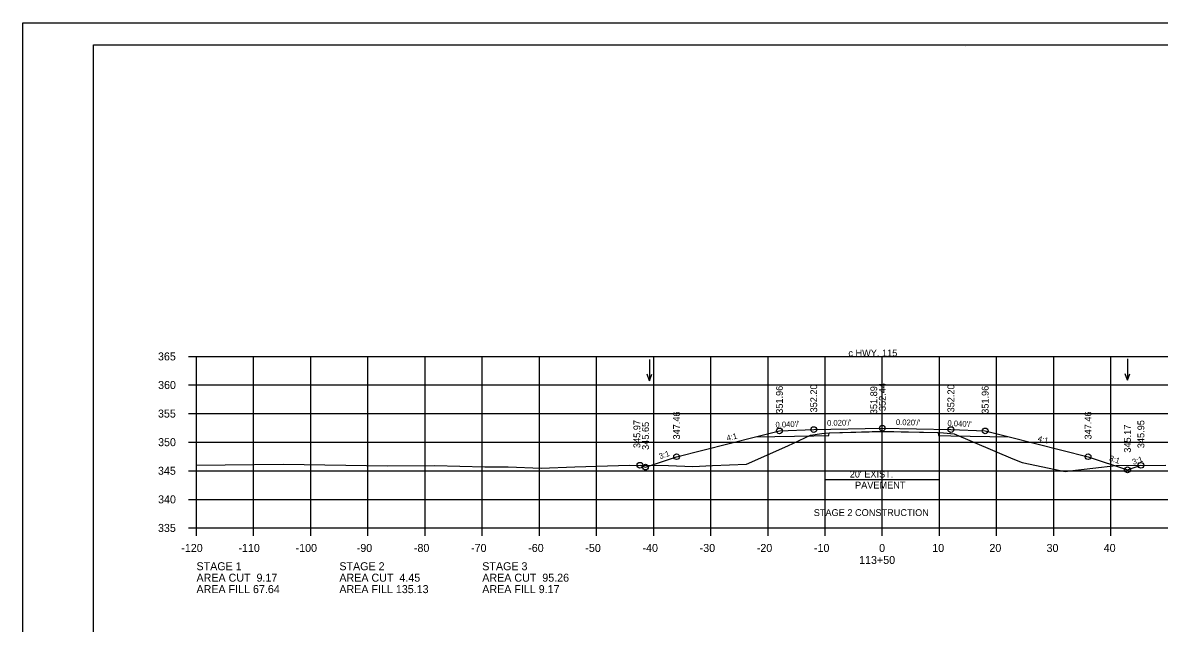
# Model space of a CAD drawing. Extents: x 1630712 to 1632516, y 782146 to 785403.
# Drawn here: x 1632182.6 to 1632381.4, y 784871.6 to 784976.7 of the extents above; entities that cross this region are included whole.
import ezdxf

# ---------------------------------------------------------------- set-up
doc = ezdxf.new("R2010")
doc.units = 0
for name, color, linetype in [('Notes', 7, 'Continuous'), ('R_Alt Surface', 7, 'Continuous'), ('R_Axis', 7, 'Continuous'), ('R_Axis Annot', 7, 'Continuous'), ('R_Border', 7, 'Continuous'), ('R_Exist Surface', 7, 'Continuous'), ('R_Fin Surface', 7, 'Continuous'), ('R_Grid', 7, 'Continuous'), ('R_No Plot', 7, 'Continuous'), ('R_Water Annot', 7, 'Continuous'), ('R_Xsect Elev', 7, 'Continuous'), ('R_Xsect Slope', 7, 'Continuous')]:
    doc.layers.add(name, color=color, linetype=linetype)

msp = doc.modelspace()

# ---------------------------------------------------------------- linework, layer by layer
at = {"layer": 'Notes'}
for p, q in [((1632322.96, 784895.06), (1632322.96, 784898.46)), ((1632342.96, 784895.06), (1632342.96, 784898.46)), ((1632322.96, 784896.76), (1632342.96, 784896.76))]:
    msp.add_line(p, q, dxfattribs=at)
at = {"layer": 'R_Alt Surface'}
msp.add_lwpolyline([(1632310.79, 784904.23), (1632320.96, 784904.43), (1632323.62, 784904.48), (1632323.67, 784904.94), (1632333.01, 784905.2), (1632342.74, 784905), (1632342.79, 784904.48), (1632344.96, 784904.43), (1632355.14, 784904.23)], dxfattribs=at)
at = {"layer": 'R_Axis'}
for p, q in [((1632211.56, 784918.31), (1632212.96, 784918.31)), ((1632212.96, 784888.31), (1632212.96, 784918.31)), ((1632211.56, 784913.31), (1632212.96, 784913.31)), ((1632211.56, 784908.31), (1632212.96, 784908.31)), ((1632211.56, 784903.31), (1632212.96, 784903.31)), ((1632211.56, 784898.31), (1632212.96, 784898.31)), ((1632211.56, 784893.31), (1632212.96, 784893.31)), ((1632211.56, 784888.31), (1632212.96, 784888.31)), ((1632212.96, 784888.31), (1632492.96, 784888.31)), ((1632212.96, 784886.91), (1632212.96, 784888.31)), ((1632222.96, 784886.91), (1632222.96, 784888.31)), ((1632232.96, 784886.91), (1632232.96, 784888.31)), ((1632242.96, 784886.91), (1632242.96, 784888.31)), ((1632252.96, 784886.91), (1632252.96, 784888.31)), ((1632262.96, 784886.91), (1632262.96, 784888.31)), ((1632272.96, 784886.91), (1632272.96, 784888.31)), ((1632282.96, 784886.91), (1632282.96, 784888.31)), ((1632292.96, 784886.91), (1632292.96, 784888.31)), ((1632302.96, 784886.91), (1632302.96, 784888.31)), ((1632312.96, 784886.91), (1632312.96, 784888.31)), ((1632322.96, 784886.91), (1632322.96, 784888.31)), ((1632332.96, 784886.91), (1632332.96, 784888.31)), ((1632342.96, 784886.91), (1632342.96, 784888.31)), ((1632352.96, 784886.91), (1632352.96, 784888.31)), ((1632362.96, 784886.91), (1632362.96, 784888.31)), ((1632372.96, 784886.91), (1632372.96, 784888.31))]:
    msp.add_line(p, q, dxfattribs=at)
at = {"layer": 'R_Border'}
for p, q in [((1632194.96, 784972.77), (1632511.14, 784972.77)), ((1632194.96, 784767.31), (1632194.96, 784972.77)), ((1632347.48, 784972.51), (1632347.48, 784972.51)), ((1632347.48, 784972.51), (1632347.48, 784972.51))]:
    msp.add_line(p, q, dxfattribs=at)
at = {"layer": 'R_Exist Surface'}
msp.add_lwpolyline([(1632212.96, 784899.31), (1632217.97, 784899.36), (1632228.2, 784899.47), (1632246.32, 784899.18), (1632254.66, 784899.23), (1632263.41, 784899), (1632267.5, 784899.02), (1632273.29, 784898.75), (1632279.16, 784899.02), (1632288.73, 784899.31), (1632295.53, 784899.21), (1632299.83, 784899.07), (1632303.24, 784899.21), (1632309.21, 784899.47), (1632316.4, 784902.69), (1632320.4, 784904.53), (1632322.39, 784904.8), (1632323.67, 784904.94), (1632331.17, 784905.15), (1632333.01, 784905.2), (1632335, 784905.16), (1632342.74, 784905), (1632343.68, 784904.93), (1632345.55, 784904.77), (1632355.79, 784900.42), (1632357.41, 784899.76), (1632364.37, 784898.31), (1632364.95, 784898.21), (1632365.78, 784898.32), (1632373.84, 784899.25), (1632382.54, 784899.26)], dxfattribs=at)
at = {"layer": 'R_Fin Surface'}
msp.add_lwpolyline([(1632290.55, 784899.28), (1632291.52, 784898.96), (1632296.96, 784900.77), (1632310.79, 784904.23), (1632314.96, 784905.27), (1632320.96, 784905.51), (1632332.96, 784905.75), (1632344.96, 784905.51), (1632350.96, 784905.27), (1632355.14, 784904.23), (1632368.96, 784900.77), (1632375.86, 784898.47), (1632378.21, 784899.26)], dxfattribs=at)
at = {"layer": 'R_Grid'}
for p, q in [((1632212.96, 784918.31), (1632492.96, 784918.31)), ((1632212.96, 784888.31), (1632212.96, 784918.31)), ((1632222.96, 784888.31), (1632222.96, 784918.31)), ((1632232.96, 784888.31), (1632232.96, 784918.31)), ((1632242.96, 784888.31), (1632242.96, 784918.31)), ((1632252.96, 784888.31), (1632252.96, 784918.31)), ((1632262.96, 784888.31), (1632262.96, 784918.31)), ((1632272.96, 784888.31), (1632272.96, 784918.31)), ((1632282.96, 784888.31), (1632282.96, 784918.31)), ((1632292.96, 784888.31), (1632292.96, 784918.31)), ((1632302.96, 784888.31), (1632302.96, 784918.31)), ((1632312.96, 784888.31), (1632312.96, 784918.31)), ((1632322.96, 784888.31), (1632322.96, 784918.31)), ((1632332.96, 784888.31), (1632332.96, 784918.31)), ((1632342.96, 784888.31), (1632342.96, 784918.31)), ((1632352.96, 784888.31), (1632352.96, 784918.31)), ((1632362.96, 784888.31), (1632362.96, 784918.31)), ((1632372.96, 784888.31), (1632372.96, 784918.31)), ((1632212.96, 784913.31), (1632492.96, 784913.31)), ((1632212.96, 784908.31), (1632492.96, 784908.31)), ((1632212.96, 784903.31), (1632492.96, 784903.31)), ((1632212.96, 784898.31), (1632492.96, 784898.31)), ((1632212.96, 784893.31), (1632492.96, 784893.31)), ((1632212.96, 784888.31), (1632492.96, 784888.31))]:
    msp.add_line(p, q, dxfattribs=at)
at = {"layer": 'R_No Plot'}
msp.add_line((1632182.56, 784976.66), (1632515.9, 784976.66), dxfattribs=at)
msp.add_lwpolyline([(1632182.56, 784976.66), (1632515.9, 784976.66), (1632515.9, 784763.32), (1632182.56, 784763.32)], close=True, dxfattribs=at)
for centre in [(1632320.96, 784905.51), (1632332.96, 784905.75), (1632344.96, 784905.51), (1632314.96, 784905.27), (1632350.96, 784905.27), (1632296.96, 784900.77), (1632368.96, 784900.77), (1632290.55, 784899.28), (1632291.52, 784898.96), (1632375.86, 784898.47), (1632378.21, 784899.26)]:
    msp.add_circle(centre, 0.5, dxfattribs=at)
at = {"layer": 'R_Water Annot'}
for p, q in [((1632375.86, 784917.91), (1632375.86, 784914.14)), ((1632292.24, 784917.79), (1632292.24, 784914.02)), ((1632292.24, 784914.02), (1632291.82, 784915.18)), ((1632292.24, 784914.02), (1632292.66, 784915.18)), ((1632375.86, 784914.14), (1632375.44, 784915.29)), ((1632375.86, 784914.14), (1632376.28, 784915.29))]:
    msp.add_line(p, q, dxfattribs=at)

# ---------------------------------------------------------------- texts
at = {"layer": 'Notes'}
for s, p in [('c HWY. 115', (1632327.02, 784918.31)), ("20' EXIST.", (1632327.26, 784897.12)), ('PAVEMENT', (1632328.19, 784895.2)), ('STAGE 2 CONSTRUCTION', (1632320.96, 784890.39))]:
    msp.add_text(s, height=1.2, dxfattribs=at).set_placement(p)
at = {"layer": 'R_Axis'}
msp.add_text('-', height=0.0001, dxfattribs=at).set_placement((1632212.96, 784888.31))
at = {"layer": 'R_Axis Annot'}
for s, p in [('365', (1632206.22, 784917.61)), ('360', (1632206.24, 784912.61)), ('355', (1632206.22, 784907.61)), ('350', (1632206.24, 784902.61)), ('345', (1632206.22, 784897.61)), ('340', (1632206.24, 784892.61)), ('335', (1632206.22, 784887.61)), ('-120', (1632210.3, 784884.11)), ('-110', (1632220.3, 784884.11)), ('-100', (1632230.3, 784884.11)), ('-90', (1632241, 784884.11)), ('-80', (1632251, 784884.11)), ('-70', (1632261, 784884.11)), ('-60', (1632271, 784884.11)), ('-50', (1632281, 784884.11)), ('-40', (1632291, 784884.11)), ('-30', (1632301, 784884.11)), ('-20', (1632311, 784884.11)), ('-10', (1632321, 784884.11)), ('0', (1632332.4, 784884.11)), ('10', (1632341.7, 784884.11)), ('20', (1632351.7, 784884.11)), ('30', (1632361.7, 784884.11)), ('40', (1632371.7, 784884.11)), ('STAGE 1', (1632212.96, 784880.91)), ('STAGE 2', (1632237.96, 784880.91)), ('STAGE 3', (1632262.96, 784880.91)), ('113+50', (1632328.9, 784882.01)), ('AREA CUT  9.17', (1632212.96, 784878.91)), ('AREA CUT  4.45', (1632237.96, 784878.91)), ('AREA CUT  95.26', (1632262.96, 784878.91)), ('AREA FILL 67.64', (1632212.96, 784876.91)), ('AREA FILL 135.13', (1632237.96, 784876.91)), ('AREA FILL 9.17', (1632262.96, 784876.91))]:
    msp.add_text(s, height=1.4, dxfattribs=at).set_placement(p)
at = {"layer": 'R_Xsect Elev'}
for s, p in [('351.96', (1632315.56, 784908.27)), ('352.20', (1632321.56, 784908.51)), ('351.89', (1632332.06, 784908.2)), ('352.44', (1632333.56, 784908.75)), ('352.20', (1632345.56, 784908.51)), ('351.96', (1632351.56, 784908.27)), ('347.46', (1632297.56, 784903.77)), ('347.46', (1632369.56, 784903.77)), ('345.97', (1632290.62, 784902.28)), ('345.65', (1632292.12, 784901.96)), ('345.17', (1632376.46, 784901.47)), ('345.95', (1632378.81, 784902.26))]:
    msp.add_text(s, height=1.2, rotation=90, dxfattribs=at).set_placement(p)
at = {"layer": 'R_Xsect Slope'}
for s, rotation, p in [("0.040'/'", 2.2906, (1632314.29, 784905.85)), ("0.020'/'", 1.1458, (1632323.3, 784906.16)), ("0.020'/'", 358.8542, (1632335.33, 784906.31)), ("0.040'/'", 357.7094, (1632344.34, 784906.14)), ('4:1', 14.0362, (1632305.84, 784903.51)), ('4:1', 345.9638, (1632360.09, 784903.51)), ('3:1', 18.4349, (1632294.08, 784900.34)), ('3:1', 341.5651, (1632372.57, 784900.1)), ('3:1', 18.4349, (1632376.88, 784899.34))]:
    msp.add_text(s, height=1, rotation=rotation, dxfattribs=at).set_placement(p)

doc.saveas('drawing.dxf')
